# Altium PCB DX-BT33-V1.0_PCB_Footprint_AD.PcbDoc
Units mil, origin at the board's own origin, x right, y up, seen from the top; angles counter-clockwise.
Board outline 6000 x 4000 mil, 2 copper layers (Top Layer, Bottom Layer); 1 components, 15 nets, 26 pads, 0 vias.
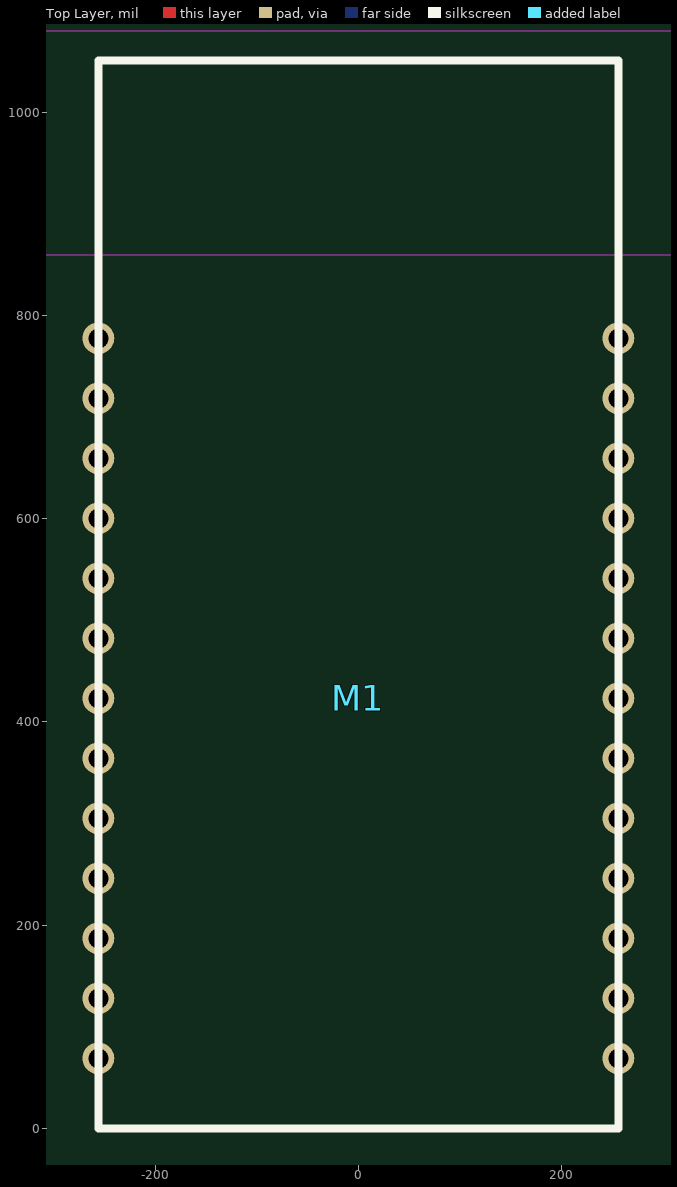
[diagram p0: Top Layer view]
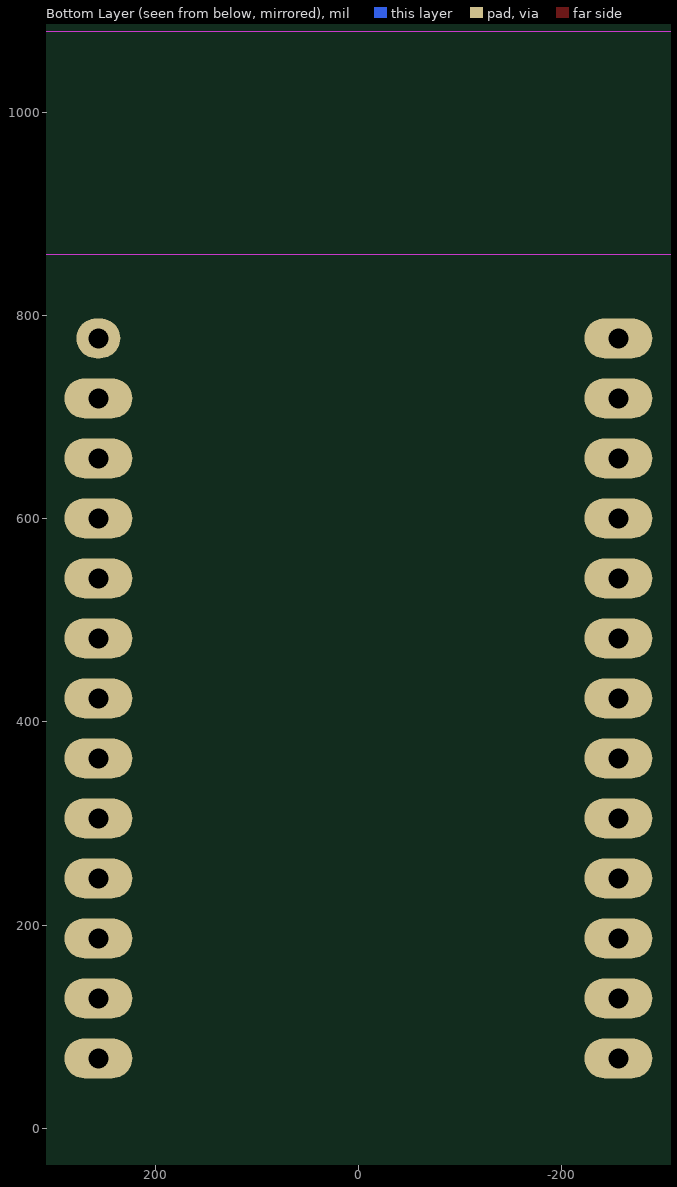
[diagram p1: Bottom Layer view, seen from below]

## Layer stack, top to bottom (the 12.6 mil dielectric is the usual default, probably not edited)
Top Solder: solder mask 0.4, Solder Resist, Dk 3.5
Top Layer: signal copper 1.4
Dielectric 1: dielectric 12.6, FR-4, Dk 4.8
Bottom Layer: signal copper 1.4
Bottom Solder: solder mask 0.4, Solder Resist, Dk 3.5

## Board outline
-2805,-1405 3195,-1405 3195,2595 -2805,2595

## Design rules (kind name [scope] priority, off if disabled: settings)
Clearance [All] p1: gap=10 ignorepadtopadclearanceinfootprint=FALSE except(0: Arc-Hole Track-Hole SMDPad-Hole THPad-Hole Via-Hole Fill-Hole Poly-Hole Region-Hole Text-Hole)
PolygonConnect [All] p1: connectstyle=Relief reliefconductorwidth=10 reliefentries=4 polygonreliefangle="90 Angle" airgapwidth=10
RoutingVias [All] p1: holewidth=28 width=50 viastyle="Through Hole" minholewidth=28 minwidth=50 maxholewidth=28 maxwidth=50
SolderMaskExpansion [All] p1: expansion=4 istentingtop=FALSE
Width [All] p1: maxlimit=10 minlimit=10 preferedwidth=10
30 further rules are at their usual default settings.

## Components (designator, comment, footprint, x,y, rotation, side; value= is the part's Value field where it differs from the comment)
M1 "DX-BT39" DX-BT39 0,0 r0 top

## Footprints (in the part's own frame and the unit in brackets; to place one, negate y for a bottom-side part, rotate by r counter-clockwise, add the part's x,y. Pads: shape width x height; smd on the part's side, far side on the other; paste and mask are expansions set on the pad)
DX-BT39 [mm]
  round 0.8 / inner round 0.8 / far side oval 1.7x1 hole 0.5 mask-2539.97: 1(-6.5,19.75) 2(-6.5,18.25) 3(-6.5,16.75) 4(-6.5,15.25) 5(-6.5,13.75) 6(-6.5,12.25) 7(-6.5,10.75) 8(-6.5,9.25) 9(-6.5,7.75) 10(-6.5,6.25) 11(-6.5,4.75) 12(-6.5,3.25) 13(-6.5,1.75) 14(6.5,1.75) 15(6.5,3.25) 16(6.5,4.75) 17(6.5,6.25) 18(6.5,7.75) 19(6.5,9.25) 20(6.5,10.75) 21(6.5,12.25) 22(6.5,13.75) 23(6.5,15.25) 24(6.5,16.75) 25(6.5,18.25)
  round 0.8 / inner round 0.8 / far side oval 1.1x1 hole 0.5 mask-2539.97: 26(6.5,19.75)
  Keep-Out Layer region: -7.874,21.844 7.874,21.844 7.874,27.432 -7.874,27.432
  silkscreen extent -6.5,0 6.5,26.7

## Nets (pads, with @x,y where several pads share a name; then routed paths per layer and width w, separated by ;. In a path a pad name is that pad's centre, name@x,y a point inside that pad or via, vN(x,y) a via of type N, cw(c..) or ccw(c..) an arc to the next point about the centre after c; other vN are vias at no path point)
ANT3: 
GND: 
P00/TX/D-: 
P01/RX/D+: 
P02: 
P03: 
P04: 
P05: 
P06: 
P07: 
P10: 
P11: 
P32: 
RSTN: 
VBAT: 
pads on no net: M1.1 M1.2 M1.3 M1.4 M1.5 M1.6 M1.7 M1.8 M1.9 M1.10 M1.11 M1.12 M1.13 M1.14 M1.15 M1.16 M1.17 M1.18 M1.19 M1.20 M1.21 M1.22 M1.23 M1.24 M1.25 M1.26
